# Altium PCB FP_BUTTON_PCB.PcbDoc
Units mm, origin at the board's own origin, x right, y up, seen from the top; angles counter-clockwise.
Board outline 25.4 x 26 mm, 2 copper layers (Top Layer, Bottom Layer); 3 components, 3 nets, 10 pads, 0 vias.
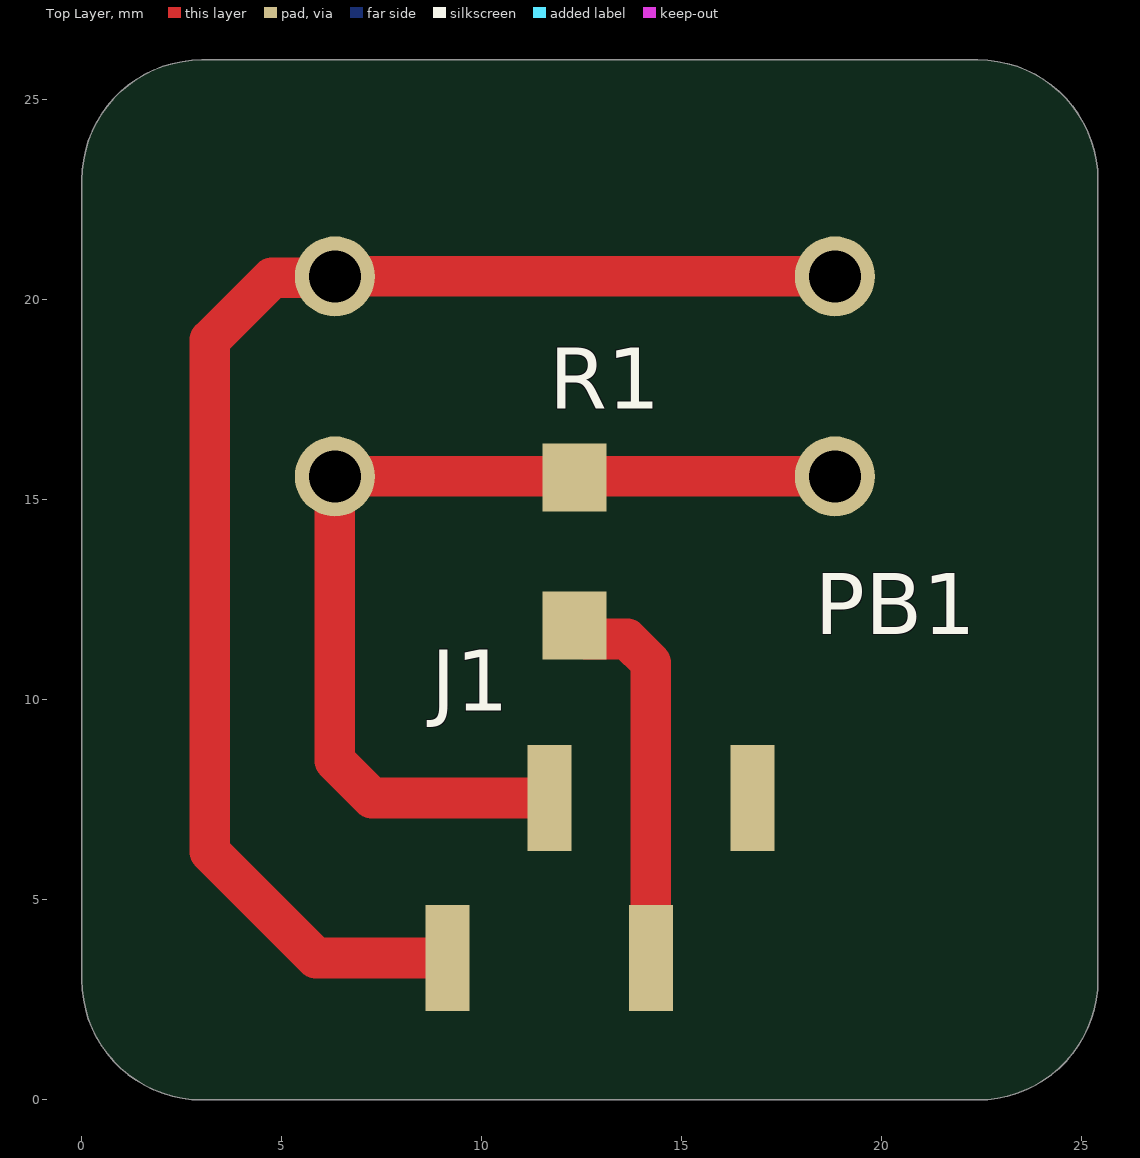
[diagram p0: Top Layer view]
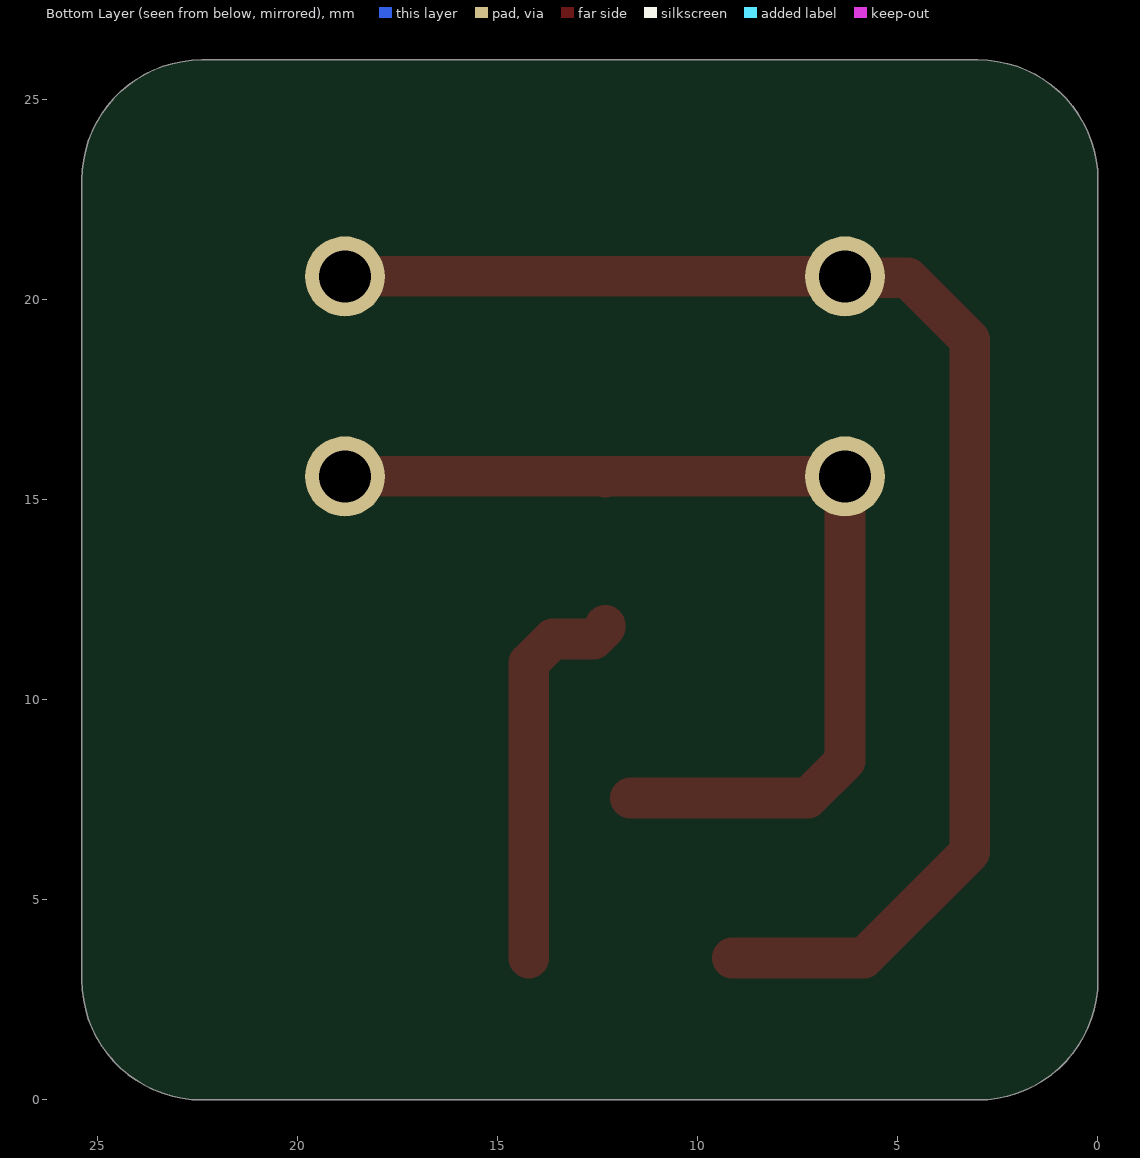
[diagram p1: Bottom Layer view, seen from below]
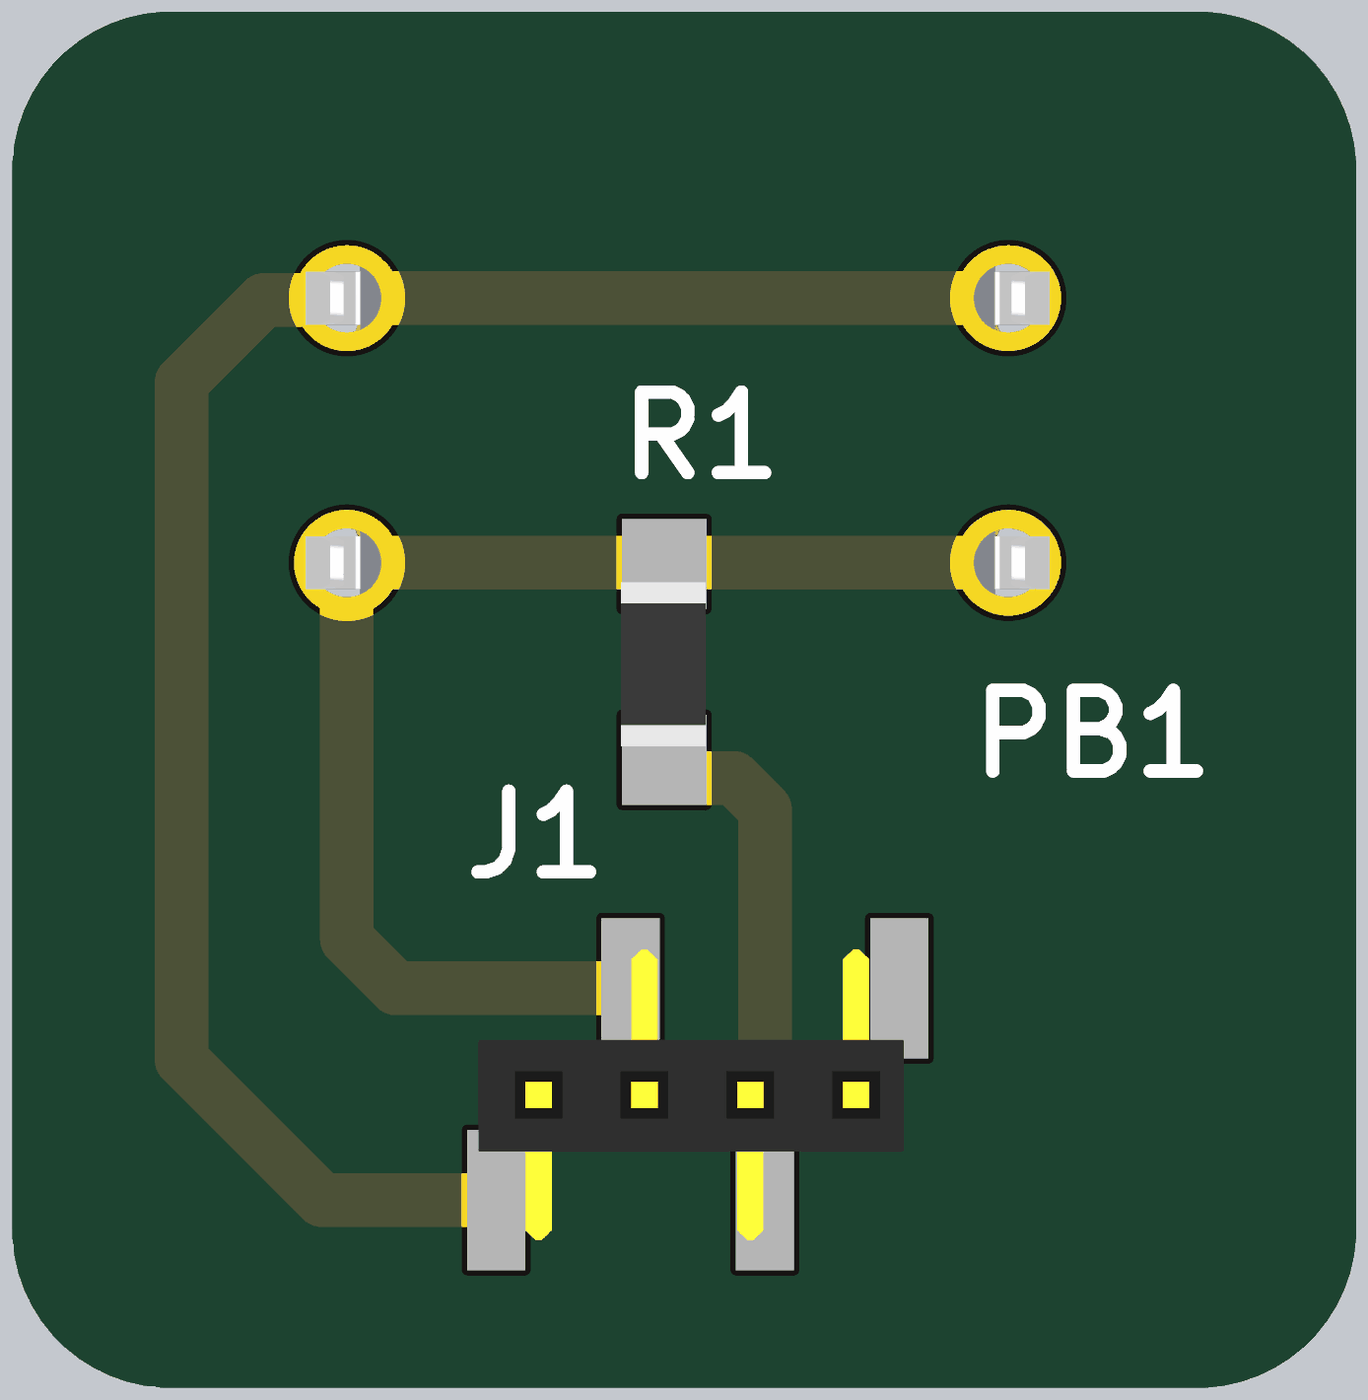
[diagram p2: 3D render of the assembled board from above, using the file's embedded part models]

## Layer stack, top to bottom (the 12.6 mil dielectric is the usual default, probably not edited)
Top Solder: solder mask 0.0102, Solder Resist, Dk 3.5
Top Layer: signal copper 0.0356
Dielectric 1: dielectric 0.32, FR-4, Dk 4.8
Bottom Layer: signal copper 0.0356
Bottom Solder: solder mask 0.0102, Solder Resist, Dk 3.5

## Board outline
0,3 ccw(c3,3) 3,0 22.4,0 ccw(c22.4,3) 25.4,3 25.4,23 ccw(c22.4,23) 22.4,26 3,26 ccw(c3,23) 0,23

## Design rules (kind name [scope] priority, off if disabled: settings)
Clearance [All] p1: gap=0.254 ignorepadtopadclearanceinfootprint=FALSE
PolygonConnect [All] p1: connectstyle=Relief reliefconductorwidth=0.254 reliefentries=4 polygonreliefangle="90 Angle" airgapwidth=0.254
RoutingVias [All] p1: holewidth=0.711 width=1.27 viastyle="Through Hole" minholewidth=0.711 minwidth=1.27 maxholewidth=0.711 maxwidth=1.27
SolderMaskExpansion [All] p1: expansion=0.102 istentingtop=FALSE
SupplyNets "Schematic Supply Nets_1" [InNet('GND')] p1: voltage=0.000
SupplyNets "Schematic Supply Nets" [InNet('3V3')] p2: voltage=0.000
Width [All] p1: maxlimit=1.27 minlimit=0.254 preferedwidth=1.016 minimp=50.000000 maximp=50.000000 favimp=50.000000
30 further rules are at their usual default settings.

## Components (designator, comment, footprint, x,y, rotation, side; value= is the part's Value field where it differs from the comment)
J1 "Header 1x4" HDR4X1_FEMALE 9.145,3.547 r90 top
PB1 "Push_button" button_12x12 12.574,18.088 r0 top
R1 "R10K" RES1206 12.32,11.865 r90 top

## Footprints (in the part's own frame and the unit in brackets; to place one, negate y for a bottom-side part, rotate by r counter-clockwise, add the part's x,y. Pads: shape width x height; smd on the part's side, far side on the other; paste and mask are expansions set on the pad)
button_12x12 [mm]
  round 2 hole 1.3: 1(-6.25,2.5) 1(6.25,2.5) 2(-6.25,-2.5) 2(6.25,-2.5)
  body extent -7.03,-6.4 7.03,6.4, height 12
HDR4X1_FEMALE [mm]
  rect 2.65x1.1 smd: 1(0,0) 2(4,-2.54) 3(0,-5.08) 4(4,-7.62)
  body extent -0.76,-7.7 4.74,0.34, height 2.33
RES1206 [mm]
  rect 1.7x1.6 smd: 1(0,0) 2(3.7,0)
  body extent 0.25,-0.79 3.35,0.81, height 0.55

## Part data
PB1: "PTS636SM25FSMTR LFS"

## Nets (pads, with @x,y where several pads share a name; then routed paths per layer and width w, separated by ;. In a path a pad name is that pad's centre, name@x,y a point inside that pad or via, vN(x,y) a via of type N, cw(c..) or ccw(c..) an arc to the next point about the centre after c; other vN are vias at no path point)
3V3: J1.1 PB1.1 | length 36.1
  Top Layer w1.016: J1.1 5.853,3.547 3.2,6.2 3.2,19 4.753,20.552 6.288,20.552 6.324,20.588 PB1.1@18.824,20.588
GND: J1.3 R1.1 | length 9.7
  Top Layer w1.016: R1.1 12.32,11.815 12.612,11.523 13.63,11.523 14.225,10.928 J1.3
NetJ1_2: J1.2 PB1.2 R1.2 | length 25.4
  Top Layer w1.016: J1.2 7.253,7.547 6.324,8.476 6.324,15.588 12.297,15.588 R1.2 12.343,15.588 PB1.2@18.824,15.588
pads on no net: J1.4

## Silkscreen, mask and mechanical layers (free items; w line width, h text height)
Mechanical 1:
  the board outline again, w0.254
